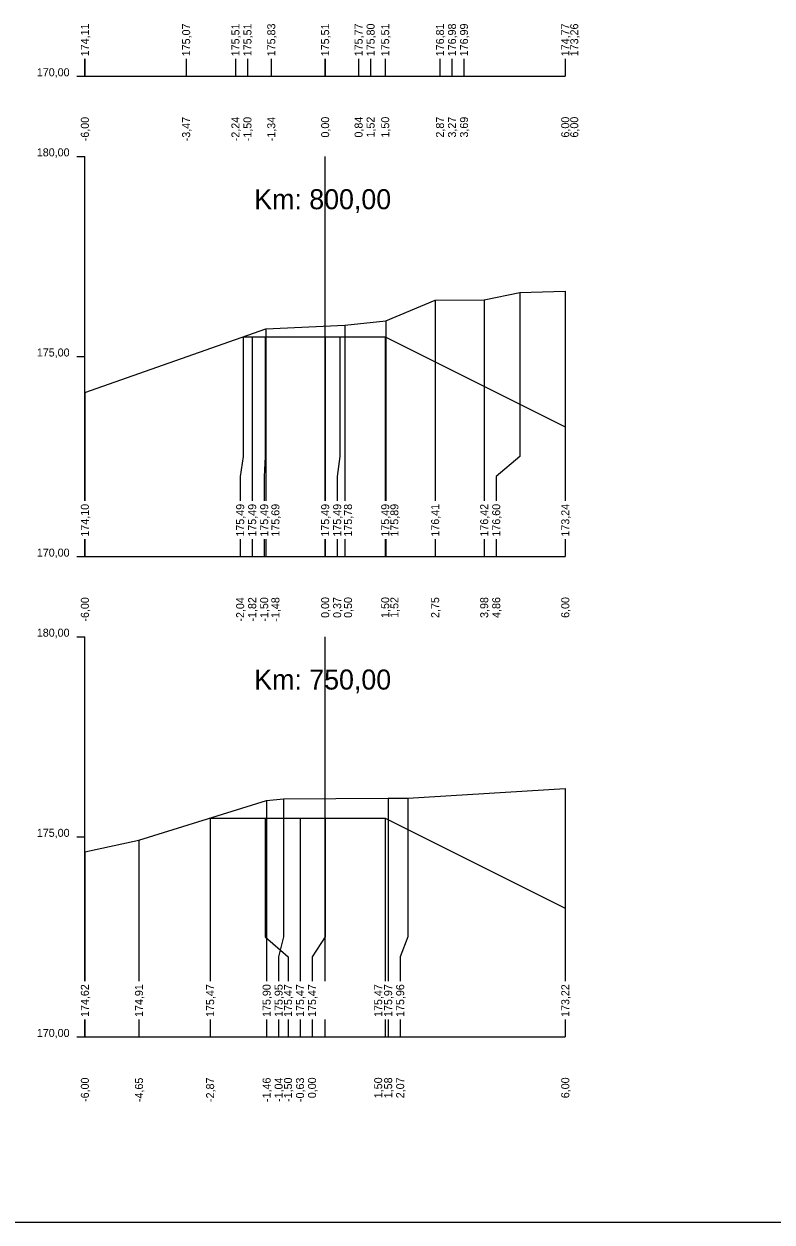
# Model space of a CAD drawing. Extents: x -614174 to -599765, y -1185887 to -1181080.
# Drawn here: x -608768.35 to -608749.66, y -1184519.11 to -1184489.18 of the extents above; entities that cross this region are included whole.
import ezdxf

# ---------------------------------------------------------------- set-up
doc = ezdxf.new("R2010")
doc.units = 0
for name, color, linetype in [('11', 7, 'Continuous'), ('16', 7, 'Continuous'), ('21', 7, 'Continuous'), ('28', 7, 'Continuous'), ('59', 7, 'Continuous'), ('8', 7, 'Continuous'), ('návrh', 7, 'Continuous')]:
    doc.layers.add(name, color=color, linetype=linetype)

msp = doc.modelspace()

# ---------------------------------------------------------------- linework, layer by layer
for points in [[(-608766.825, -1184498.386), (-608762.301, -1184496.799), (-608760.329, -1184496.706), (-608759.307, -1184496.597), (-608758.075, -1184496.08), (-608756.85, -1184496.071), (-608755.963, -1184495.886), (-608754.825, -1184495.852)], [(-608762.869, -1184496.998), (-608762.646, -1184496.998), (-608762.323, -1184496.998), (-608760.823, -1184496.998), (-608760.458, -1184496.998), (-608759.323, -1184496.998), (-608754.825, -1184499.247)], [(-608762.323, -1184496.998), (-608762.323, -1184496.998), (-608762.323, -1184496.998)], [(-608760.823, -1184496.998), (-608760.823, -1184496.998), (-608760.823, -1184496.998)], [(-608759.323, -1184496.998), (-608759.323, -1184496.998), (-608759.323, -1184496.998)], [(-608766.825, -1184509.863), (-608765.473, -1184509.573), (-608762.285, -1184508.582), (-608761.865, -1184508.538), (-608759.249, -1184508.519), (-608758.754, -1184508.525), (-608754.825, -1184508.277)], [(-608763.696, -1184509.021), (-608762.323, -1184509.021), (-608761.451, -1184509.021), (-608760.823, -1184509.021), (-608759.323, -1184509.021), (-608754.825, -1184511.27)], [(-608762.323, -1184509.021), (-608762.323, -1184509.021), (-608762.323, -1184509.021)], [(-608760.823, -1184509.021), (-608760.823, -1184509.021), (-608760.823, -1184509.021)], [(-608759.323, -1184509.021), (-608759.323, -1184509.021), (-608759.323, -1184509.021)]]:
    msp.add_lwpolyline(points)
at = {"layer": '11'}
for points in [[(-608766.825, -1184490.047), (-608766.825, -1184490.487)], [(-608764.295, -1184490.047), (-608764.295, -1184490.487)], [(-608763.064, -1184490.047), (-608763.064, -1184490.487)], [(-608762.764, -1184490.047), (-608762.764, -1184490.487)], [(-608762.169, -1184490.047), (-608762.169, -1184490.487)], [(-608760.823, -1184490.047), (-608760.823, -1184490.487)], [(-608759.988, -1184490.047), (-608759.988, -1184490.487)], [(-608759.688, -1184490.047), (-608759.688, -1184490.487)], [(-608759.323, -1184490.047), (-608759.323, -1184490.487)], [(-608757.955, -1184490.047), (-608757.955, -1184490.487)], [(-608757.655, -1184490.047), (-608757.655, -1184490.487)], [(-608757.355, -1184490.047), (-608757.355, -1184490.487)], [(-608754.825, -1184490.047), (-608754.825, -1184490.487)], [(-608754.825, -1184490.047), (-608754.825, -1184490.487)], [(-608755.963, -1184495.886), (-608755.963, -1184499.987), (-608756.55, -1184500.487), (-608756.55, -1184501.089)], [(-608754.825, -1184495.852), (-608754.825, -1184499.987), (-608754.825, -1184500.487), (-608754.825, -1184501.089)], [(-608758.075, -1184496.08), (-608758.075, -1184499.987), (-608758.075, -1184500.487), (-608758.075, -1184501.089)], [(-608756.85, -1184496.071), (-608756.85, -1184499.987), (-608756.85, -1184500.487), (-608756.85, -1184501.089)], [(-608759.307, -1184496.597), (-608759.307, -1184499.987), (-608759.307, -1184500.487), (-608759.307, -1184501.089)], [(-608762.301, -1184496.799), (-608762.301, -1184499.987), (-608762.301, -1184500.487), (-608762.301, -1184501.089)], [(-608760.329, -1184496.706), (-608760.329, -1184499.987), (-608760.329, -1184500.487), (-608760.329, -1184501.089)], [(-608762.869, -1184496.998), (-608762.869, -1184499.987), (-608762.946, -1184500.487), (-608762.946, -1184501.089)], [(-608762.646, -1184496.998), (-608762.646, -1184499.987), (-608762.646, -1184500.487), (-608762.646, -1184501.089)], [(-608762.323, -1184496.998), (-608762.323, -1184499.987), (-608762.346, -1184500.487), (-608762.346, -1184501.089)], [(-608760.823, -1184496.998), (-608760.823, -1184499.987), (-608760.823, -1184500.487), (-608760.823, -1184501.089)], [(-608760.458, -1184496.998), (-608760.458, -1184499.987), (-608760.523, -1184500.487), (-608760.523, -1184501.089)], [(-608759.323, -1184496.998), (-608759.323, -1184499.987), (-608759.323, -1184500.487), (-608759.323, -1184501.089)], [(-608766.825, -1184498.386), (-608766.825, -1184499.987), (-608766.825, -1184500.487), (-608766.825, -1184501.089)], [(-608754.825, -1184499.247), (-608754.825, -1184499.987), (-608754.825, -1184500.487), (-608754.825, -1184501.089)], [(-608766.825, -1184502.047), (-608766.825, -1184502.487)], [(-608762.946, -1184502.047), (-608762.946, -1184502.487)], [(-608762.646, -1184502.047), (-608762.646, -1184502.487)], [(-608762.346, -1184502.047), (-608762.346, -1184502.487)], [(-608762.301, -1184502.047), (-608762.301, -1184502.487)], [(-608760.823, -1184502.047), (-608760.823, -1184502.487)], [(-608760.523, -1184502.047), (-608760.523, -1184502.487)], [(-608760.329, -1184502.047), (-608760.329, -1184502.487)], [(-608759.323, -1184502.047), (-608759.323, -1184502.487)], [(-608759.307, -1184502.047), (-608759.307, -1184502.487)], [(-608758.075, -1184502.047), (-608758.075, -1184502.487)], [(-608756.85, -1184502.047), (-608756.85, -1184502.487)], [(-608756.55, -1184502.047), (-608756.55, -1184502.487)], [(-608754.825, -1184502.047), (-608754.825, -1184502.487)], [(-608754.825, -1184502.047), (-608754.825, -1184502.487)], [(-608754.825, -1184508.277), (-608754.825, -1184511.987), (-608754.825, -1184512.487), (-608754.825, -1184513.089)], [(-608762.285, -1184508.582), (-608762.285, -1184511.987), (-608762.285, -1184512.487), (-608762.285, -1184513.089)], [(-608761.865, -1184508.538), (-608761.865, -1184511.987), (-608761.985, -1184512.487), (-608761.985, -1184513.089)], [(-608759.249, -1184508.519), (-608759.249, -1184511.987), (-608759.249, -1184512.487), (-608759.249, -1184513.089)], [(-608758.754, -1184508.525), (-608758.754, -1184511.987), (-608758.949, -1184512.487), (-608758.949, -1184513.089)], [(-608763.696, -1184509.021), (-608763.696, -1184511.987), (-608763.696, -1184512.487), (-608763.696, -1184513.089)], [(-608762.323, -1184509.021), (-608762.323, -1184511.987), (-608761.751, -1184512.487), (-608761.751, -1184513.089)], [(-608761.451, -1184509.021), (-608761.451, -1184511.987), (-608761.451, -1184512.487), (-608761.451, -1184513.089)], [(-608760.823, -1184509.021), (-608760.823, -1184511.987), (-608761.151, -1184512.487), (-608761.151, -1184513.089)], [(-608759.323, -1184509.021), (-608759.323, -1184511.987), (-608759.323, -1184512.487), (-608759.323, -1184513.089)], [(-608765.473, -1184509.573), (-608765.473, -1184511.987), (-608765.473, -1184512.487), (-608765.473, -1184513.089)], [(-608766.825, -1184509.863), (-608766.825, -1184511.987), (-608766.825, -1184512.487), (-608766.825, -1184513.089)], [(-608754.825, -1184511.27), (-608754.825, -1184511.987), (-608754.825, -1184512.487), (-608754.825, -1184513.089)], [(-608766.825, -1184514.047), (-608766.825, -1184514.487)], [(-608765.473, -1184514.047), (-608765.473, -1184514.487)], [(-608763.696, -1184514.047), (-608763.696, -1184514.487)], [(-608762.285, -1184514.047), (-608762.285, -1184514.487)], [(-608761.985, -1184514.047), (-608761.985, -1184514.487)], [(-608761.751, -1184514.047), (-608761.751, -1184514.487)], [(-608761.451, -1184514.047), (-608761.451, -1184514.487)], [(-608761.151, -1184514.047), (-608761.151, -1184514.487)], [(-608759.323, -1184514.047), (-608759.323, -1184514.487)], [(-608759.249, -1184514.047), (-608759.249, -1184514.487)], [(-608758.949, -1184514.047), (-608758.949, -1184514.487)], [(-608754.825, -1184514.047), (-608754.825, -1184514.487)], [(-608754.825, -1184514.047), (-608754.825, -1184514.487)]]:
    msp.add_lwpolyline(points, dxfattribs=at)
at = {"layer": '16'}
for p, q in [((-608766.825, -1184490.487), (-608754.825, -1184490.487)), ((-608766.825, -1184502.487), (-608754.825, -1184502.487)), ((-608766.825, -1184514.487), (-608754.825, -1184514.487))]:
    msp.add_line(p, q, dxfattribs=at)
at = {"layer": '21'}
for p, q in [((-608767.025, -1184490.487), (-608766.825, -1184490.487)), ((-608767.025, -1184492.487), (-608766.825, -1184492.487)), ((-608767.025, -1184497.487), (-608766.825, -1184497.487)), ((-608767.025, -1184502.487), (-608766.825, -1184502.487)), ((-608767.025, -1184504.487), (-608766.825, -1184504.487)), ((-608767.025, -1184509.487), (-608766.825, -1184509.487)), ((-608767.025, -1184514.487), (-608766.825, -1184514.487))]:
    msp.add_line(p, q, dxfattribs=at)
at = {"layer": '28'}
for p, q in [((-608760.825, -1184490.487), (-608760.825, -1184490.047)), ((-608760.825, -1184501.089), (-608760.825, -1184492.487)), ((-608760.825, -1184502.487), (-608760.825, -1184502.047)), ((-608760.825, -1184513.089), (-608760.825, -1184504.487)), ((-608760.825, -1184514.487), (-608760.825, -1184514.047))]:
    msp.add_line(p, q, dxfattribs=at)
at = {"layer": '8'}
for p, q in [((-608766.825, -1184490.487), (-608766.825, -1184490.047)), ((-608766.825, -1184501.089), (-608766.825, -1184492.487)), ((-608766.825, -1184502.487), (-608766.825, -1184502.047)), ((-608766.825, -1184513.089), (-608766.825, -1184504.487)), ((-608766.825, -1184514.487), (-608766.825, -1184514.047))]:
    msp.add_line(p, q, dxfattribs=at)
at = {"layer": 'návrh'}
for p, q in [((-608772.975, -1184519.11), (-608751.975, -1184519.11)), ((-608751.975, -1184519.11), (-608730.975, -1184519.11))]:
    msp.add_line(p, q, dxfattribs=at)

# ---------------------------------------------------------------- texts
for p in [(-608762.87, -1184496.999), (-608763.696, -1184509.022)]:
    msp.add_text('+', height=0.001).set_placement(p)
at = {"layer": '16'}
for s, p in [('174,11', (-608766.725, -1184489.987)), ('175,07', (-608764.195, -1184489.987)), ('175,51', (-608762.964, -1184489.987)), ('175,51', (-608762.664, -1184489.987)), ('175,83', (-608762.069, -1184489.987)), ('175,51', (-608760.723, -1184489.987)), ('175,77', (-608759.888, -1184489.987)), ('175,80', (-608759.588, -1184489.987)), ('175,51', (-608759.223, -1184489.987)), ('176,81', (-608757.855, -1184489.987)), ('176,98', (-608757.555, -1184489.987)), ('176,99', (-608757.255, -1184489.987)), ('174,77', (-608754.725, -1184489.987)), ('173,26', (-608754.501, -1184489.987)), ('174,10', (-608766.725, -1184501.987)), ('175,49', (-608762.846, -1184501.987)), ('175,49', (-608762.546, -1184501.987)), ('175,49', (-608762.246, -1184501.987)), ('175,69', (-608761.966, -1184501.987)), ('175,49', (-608760.723, -1184501.987)), ('175,49', (-608760.423, -1184501.987)), ('175,78', (-608760.152, -1184501.987)), ('175,49', (-608759.223, -1184501.987)), ('175,89', (-608758.994, -1184501.987)), ('176,41', (-608757.975, -1184501.987)), ('176,42', (-608756.75, -1184501.987)), ('176,60', (-608756.45, -1184501.987)), ('173,24', (-608754.725, -1184501.987)), ('174,62', (-608766.725, -1184513.987)), ('174,91', (-608765.373, -1184513.987)), ('175,47', (-608763.596, -1184513.987)), ('175,90', (-608762.185, -1184513.987)), ('175,95', (-608761.885, -1184513.987)), ('175,47', (-608761.651, -1184513.987)), ('175,47', (-608761.351, -1184513.987)), ('175,47', (-608761.051, -1184513.987)), ('175,47', (-608759.398, -1184513.987)), ('175,97', (-608759.149, -1184513.987)), ('175,96', (-608758.849, -1184513.987)), ('173,22', (-608754.725, -1184513.987))]:
    msp.add_text(s, height=0.2, rotation=90, dxfattribs=at).set_placement(p)
at = {"layer": '21'}
for s, p in [('170,00', (-608768.025, -1184490.487)), ('180,00', (-608768.025, -1184492.487)), ('175,00', (-608768.025, -1184497.487)), ('170,00', (-608768.025, -1184502.487)), ('180,00', (-608768.025, -1184504.487)), ('175,00', (-608768.025, -1184509.487)), ('170,00', (-608768.025, -1184514.487))]:
    msp.add_text(s, height=0.2, dxfattribs=at).set_placement(p)
at = {"layer": '28'}
for s, p in [('Km: 800,00', (-608762.594, -1184493.808)), ('Km: 750,00', (-608762.594, -1184505.808))]:
    msp.add_text(s, height=0.5, dxfattribs=at).set_placement(p)
at = {"layer": '59'}
for s, p in [('-6,00', (-608766.725, -1184492.11)), ('-3,47', (-608764.195, -1184492.111)), ('-2,24', (-608762.964, -1184492.11)), ('-1,50', (-608762.664, -1184492.11)), ('-1,34', (-608762.069, -1184492.11)), ('0,00', (-608760.723, -1184492.017)), ('0,84', (-608759.888, -1184492.017)), ('1,52', (-608759.588, -1184492.016)), ('1,50', (-608759.223, -1184492.017)), ('2,87', (-608757.855, -1184492.018)), ('3,27', (-608757.555, -1184492.018)), ('3,69', (-608757.255, -1184492.018)), ('6,00', (-608754.725, -1184492.017)), ('6,00', (-608754.501, -1184492.017)), ('0,00', (-608760.723, -1184504.017)), ('0,50', (-608760.152, -1184504.017)), ('1,50', (-608759.223, -1184504.017)), ('6,00', (-608754.725, -1184504.017)), ('-6,00', (-608766.725, -1184504.11)), ('-2,04', (-608762.846, -1184504.11)), ('-1,82', (-608762.546, -1184504.109)), ('-1,50', (-608762.246, -1184504.11)), ('-1,48', (-608761.966, -1184504.111)), ('0,37', (-608760.423, -1184504.018)), ('1,52', (-608758.994, -1184504.016)), ('2,75', (-608757.975, -1184504.02)), ('3,98', (-608756.75, -1184504.018)), ('4,86', (-608756.45, -1184504.018)), ('-6,00', (-608766.725, -1184516.11)), ('-4,65', (-608765.373, -1184516.113)), ('-2,87', (-608763.596, -1184516.111)), ('-1,46', (-608762.185, -1184516.111)), ('-1,04', (-608761.885, -1184516.11)), ('-1,50', (-608761.651, -1184516.11)), ('-0,63', (-608761.351, -1184516.111)), ('0,00', (-608761.051, -1184516.017)), ('1,50', (-608759.398, -1184516.017)), ('1,58', (-608759.149, -1184516.018)), ('2,07', (-608758.849, -1184516.018)), ('6,00', (-608754.725, -1184516.017))]:
    msp.add_text(s, height=0.2, rotation=90, dxfattribs=at).set_placement(p)

doc.saveas('drawing.dxf')
